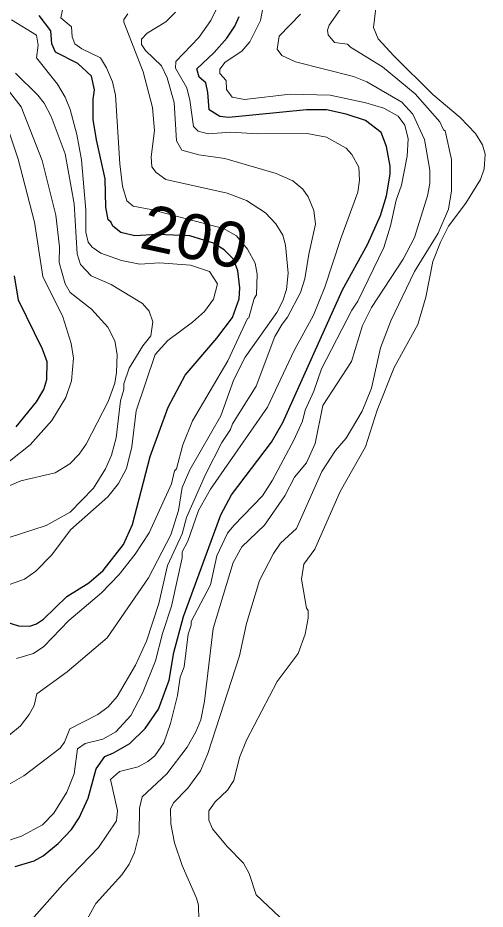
# Model space of a CAD drawing. Extents: x 474.5 to 500, y 7345.7 to 7373.4.
# Drawn here: x 475.444 to 476.272, y 7368.127 to 7369.706 of the extents above; entities that cross this region are included whole.
import ezdxf
from ezdxf.enums import TextEntityAlignment as Align

# ---------------------------------------------------------------- set-up
doc = ezdxf.new("R2010")
doc.units = 0
doc.header["$LTSCALE"] = 0.032
doc.layers.add('1', color=7, linetype='Continuous', lineweight=25)
doc.layers.add('2', color=7, linetype='Continuous', lineweight=13)
doc.layers.add('61', color=7, linetype='Continuous')

msp = doc.modelspace()

# ---------------------------------------------------------------- linework, layer by layer
at = {"layer": '1'}
for points in [[(475.4228, 7368.6359), (475.4455, 7368.6288), (475.4655, 7368.6284), (475.4774, 7368.6321), (475.4899, 7368.6407), (475.5308, 7368.6809), (475.5702, 7368.7052), (475.5951, 7368.7269), (475.6313, 7368.7727), (475.6471, 7368.8086), (475.6788, 7368.9289), (475.7107, 7369.0163), (475.741, 7369.0729), (475.7968, 7369.1383), (475.8249, 7369.1752), (475.8364, 7369.2082), (475.8377, 7369.2276), (475.8338, 7369.2579), (475.8263, 7369.2784), (475.8098, 7369.2953), (475.7912, 7369.3068), (475.7488, 7369.3202), (475.6909, 7369.3222), (475.6514, 7369.32), (475.6265, 7369.3258), (475.6127, 7369.337), (475.6088, 7369.3449), (475.604, 7369.3484), (475.6001, 7369.371), (475.5991, 7369.4212), (475.5835, 7369.4898), (475.5777, 7369.5259), (475.5777, 7369.562), (475.58, 7369.5789), (475.5744, 7369.6029), (475.5505, 7369.6251), (475.5107, 7369.6453), (475.5043, 7369.6604), (475.5027, 7369.6832), (475.4818, 7369.7104)], [(475.7834, 7369.5434), (475.781, 7369.5741), (475.7772, 7369.591), (475.7657, 7369.6009), (475.7613, 7369.6161), (475.7924, 7369.6448), (475.8147, 7369.6701), (475.8285, 7369.6916), (475.8362, 7369.7084)], [(475.4391, 7368.2021), (475.4732, 7368.2121), (475.4889, 7368.221), (475.5156, 7368.2428), (475.5391, 7368.268), (475.5531, 7368.2884), (475.5689, 7368.3235), (475.583, 7368.3752), (475.5984, 7368.3974), (475.6139, 7368.4036), (475.6426, 7368.42), (475.6699, 7368.4467), (475.6932, 7368.481), (475.7125, 7368.5325), (475.7207, 7368.5814), (475.7376, 7368.6452), (475.8041, 7368.8256), (475.8227, 7368.8612), (475.8939, 7368.9544), (475.9137, 7368.9889), (476.0195, 7369.2245), (476.0642, 7369.3045), (476.0867, 7369.3558), (476.0978, 7369.3909), (476.1042, 7369.4293), (476.1041, 7369.4436), (476.0978, 7369.4781), (476.088, 7369.5033), (476.0606, 7369.5241), (476.0263, 7369.5358), (475.9912, 7369.543), (475.9555, 7369.543), (475.8179, 7369.5295), (475.8024, 7369.5312), (475.7834, 7369.5434)], [(475.4412, 7368.9813), (475.4773, 7369.0255), (475.49, 7369.0479), (475.4954, 7369.0651), (475.4962, 7369.0967), (475.4878, 7369.1191), (475.4455, 7369.2058), (475.438, 7369.2489)]]:
    msp.add_lwpolyline(points, dxfattribs=at)
at = {"layer": '2'}
for points in [[(475.9088, 7368.1125), (475.8665, 7368.1519), (475.8542, 7368.1898), (475.8443, 7368.2082), (475.815, 7368.2377), (475.7892, 7368.2688), (475.7827, 7368.2847), (475.7826, 7368.3007), (475.794, 7368.317), (475.8157, 7368.3373), (475.8272, 7368.3549), (475.837, 7368.3953), (475.8494, 7368.4264), (475.9038, 7368.5304), (475.9413, 7368.5799), (475.9536, 7368.6142), (475.9589, 7368.6423), (475.9589, 7368.6557), (475.9558, 7368.6603), (475.9471, 7368.7117), (475.9512, 7368.738), (475.9704, 7368.7649), (476.0154, 7368.8668), (476.0601, 7368.9458), (476.0811, 7369.0112), (476.1112, 7369.0865), (476.153, 7369.163), (476.1671, 7369.2115), (476.18, 7369.2742), (476.1932, 7369.3087), (476.2077, 7369.337), (476.2384, 7369.3781), (476.264, 7369.4198), (476.2709, 7369.4386), (476.2725, 7369.4648), (476.2679, 7369.4812), (476.2554, 7369.5011), (476.2282, 7369.5299), (476.1799, 7369.5701), (476.1105, 7369.6387), (476.083, 7369.669), (476.0746, 7369.6891), (476.0802, 7369.739)], [(475.884, 7369.7526), (475.8744, 7369.7018), (475.8555, 7369.664), (475.8411, 7369.6469), (475.8116, 7369.6274)], [(476.0198, 7369.7272), (475.9962, 7369.6933), (475.9933, 7369.6842), (475.9939, 7369.6763)], [(475.4115, 7368.243), (475.4509, 7368.2558), (475.4881, 7368.276), (475.5082, 7368.297), (475.5312, 7368.3342), (475.5441, 7368.3664), (475.5499, 7368.411), (475.5636, 7368.4205), (475.5945, 7368.4281), (475.6177, 7368.4407), (475.6445, 7368.4698), (475.6653, 7368.5097), (475.688, 7368.5666), (475.7006, 7368.6155), (475.7166, 7368.6637), (475.7356, 7368.7492), (475.7357, 7368.7597), (475.7454, 7368.7787), (475.7643, 7368.8334), (475.7854, 7368.8711), (475.8866, 7369.0163), (475.9337, 7369.1168), (475.9683, 7369.1795), (475.9881, 7369.2289), (476.0168, 7369.315), (476.0467, 7369.3971), (476.0499, 7369.4187), (476.0483, 7369.4417), (476.0363, 7369.464), (476.0262, 7369.475), (475.9911, 7369.4945), (475.9569, 7369.5015), (475.869, 7369.5007), (475.8215, 7369.5039), (475.7813, 7369.5008), (475.764, 7369.5056), (475.7555, 7369.5138), (475.749, 7369.5603), (475.7435, 7369.5821), (475.7237, 7369.6173), (475.724, 7369.6289), (475.7647, 7369.6712), (475.7865, 7369.7015), (475.7954, 7369.7209)], [(475.5235, 7369.7203), (475.5202, 7369.706), (475.539, 7369.6901), (475.5407, 7369.6724), (475.5452, 7369.6602), (475.5577, 7369.6512), (475.5904, 7369.6354), (475.6014, 7369.6175), (475.612, 7369.5931), (475.6175, 7369.5693), (475.6248, 7369.4476), (475.6296, 7369.408), (475.6374, 7369.382), (475.6484, 7369.3724), (475.6797, 7369.3663), (475.8089, 7369.3327), (475.8318, 7369.3202), (475.8514, 7369.2964), (475.8648, 7369.2715), (475.8681, 7369.2517), (475.8672, 7369.2152)], [(475.5609, 7368.0981), (475.5826, 7368.1368), (475.6287, 7368.1876), (475.6413, 7368.2066), (475.6508, 7368.227), (475.659, 7368.2604), (475.6598, 7368.3055), (475.6647, 7368.3256), (475.7081, 7368.3668), (475.7444, 7368.414), (475.7599, 7368.4407), (475.7683, 7368.4621), (475.7747, 7368.4953), (475.7904, 7368.6239), (475.8256, 7368.7412), (475.8411, 7368.7686), (475.8814, 7368.8073), (475.9174, 7368.8591), (475.9347, 7368.8923), (475.956, 7368.9178), (475.971, 7368.9522), (475.9847, 7369.0192), (476.0355, 7369.0971), (476.0549, 7369.1609), (476.0708, 7369.1931), (476.1272, 7369.2787), (476.147, 7369.3167), (476.1704, 7369.3909), (476.1743, 7369.4124), (476.1743, 7369.4364), (476.1649, 7369.4909), (476.1442, 7369.5356), (476.1246, 7369.557), (476.0625, 7369.5926), (476.0393, 7369.6021), (475.936, 7369.6285), (475.9121, 7369.6392), (475.904, 7369.6507), (475.9072, 7369.6738), (475.9454, 7369.7125)], [(475.8267, 7369.0654), (475.8472, 7369.1048), (475.903, 7369.1838), (475.9141, 7369.205), (475.9206, 7369.2247), (475.923, 7369.254), (475.9183, 7369.3032), (475.9139, 7369.3211), (475.9015, 7369.3412), (475.8829, 7369.3605), (475.8497, 7369.3826), (475.8152, 7369.3955), (475.7063, 7369.4198), (475.6891, 7369.4324), (475.6819, 7369.4424), (475.6806, 7369.4598), (475.6861, 7369.5066), (475.6829, 7369.5473), (475.6663, 7369.6106), (475.632, 7369.6986), (475.632, 7369.703), (475.639, 7369.7136)], [(475.7238, 7369.7164), (475.7065, 7369.6991), (475.6732, 7369.6792), (475.6631, 7369.6682), (475.6631, 7369.6588), (475.6703, 7369.6482), (475.6988, 7369.6214), (475.709, 7369.6002), (475.7211, 7369.5561), (475.7252, 7369.4882), (475.7351, 7369.4719), (475.7649, 7369.4634), (475.8109, 7369.4568), (475.9022, 7369.4301), (475.9313, 7369.4172), (475.9494, 7369.4026), (475.9589, 7369.3891), (475.9686, 7369.3649)], [(475.4072, 7368.6943), (475.4562, 7368.7113), (475.4763, 7368.7255), (475.5041, 7368.7546), (475.5374, 7368.7992), (475.6034, 7368.8572), (475.6227, 7368.8812), (475.6367, 7368.9075), (475.6463, 7368.9458), (475.6536, 7369.0099), (475.6876, 7369.1096), (475.7101, 7369.1344), (475.7536, 7369.1668), (475.7747, 7369.1857), (475.7907, 7369.2074), (475.7979, 7369.2349), (475.7841, 7369.2566), (475.7499, 7369.2678), (475.6952, 7369.2718), (475.6604, 7369.2695), (475.6281, 7369.2763), (475.5915, 7369.2892), (475.5758, 7369.3001), (475.5688, 7369.3088), (475.5649, 7369.3265), (475.5649, 7369.3654), (475.5569, 7369.4547), (475.5488, 7369.4997), (475.537, 7369.5436), (475.5283, 7369.5659), (475.5146, 7369.5885), (475.4772, 7369.6351), (475.4802, 7369.6578), (475.477, 7369.6754), (475.4327, 7369.7024)], [(475.9939, 7369.6763), (476.0055, 7369.6627), (476.0282, 7369.6595), (476.034, 7369.654), (476.0906, 7369.6195), (476.1484, 7369.5714), (476.1921, 7369.522), (476.1985, 7369.508), (476.2016, 7369.5058), (476.2126, 7369.455), (476.2126, 7369.3997), (476.2077, 7369.3674), (476.1892, 7369.3245), (476.1474, 7369.2569), (476.1051, 7369.1691), (476.0867, 7369.1213), (476.0709, 7369.0501), (476.0546, 7369.0091), (476.0261, 7368.9615), (476.0072, 7368.9396), (475.9829, 7368.9023), (475.938, 7368.801), (475.9097, 7368.7755), (475.8974, 7368.757), (475.8727, 7368.7091), (475.8496, 7368.6328), (475.8371, 7368.5759), (475.7811, 7368.4027), (475.7678, 7368.3717), (475.7457, 7368.3412), (475.7203, 7368.3151), (475.715, 7368.3038), (475.7152, 7368.2782), (475.7218, 7368.2443), (475.7355, 7368.2041), (475.761, 7368.1464), (475.7643, 7368.1337), (475.7651, 7368.1076)], [(475.8116, 7369.6274), (475.8019, 7369.6153), (475.802, 7369.6075), (475.8135, 7369.5949), (475.8138, 7369.579), (475.824, 7369.5655), (475.8458, 7369.5613), (475.927, 7369.5709), (475.9975, 7369.5693), (476.0609, 7369.5559), (476.093, 7369.5462), (476.1181, 7369.5322), (476.1301, 7369.5159), (476.136, 7369.4916), (476.1345, 7369.4611), (476.1241, 7369.4098), (476.1147, 7369.3829), (476.1048, 7369.3375), (476.0928, 7369.2992), (476.047, 7369.2044), (476.0361, 7369.1883), (475.9821, 7369.0844), (475.9685, 7369.0447), (475.9534, 7369.0107), (475.9485, 7368.9916), (475.9333, 7368.9581), (475.8954, 7368.8869), (475.878, 7368.859), (475.8267, 7368.8069), (475.816, 7368.7929), (475.797, 7368.753), (475.7857, 7368.7012), (475.7516, 7368.6364), (475.7515, 7368.6299), (475.7459, 7368.6142), (475.7388, 7368.5563), (475.7316, 7368.5376), (475.7269, 7368.5056), (475.7148, 7368.456), (475.7028, 7368.4212), (475.6869, 7368.3983), (475.6745, 7368.3881), (475.6572, 7368.3791), (475.6244, 7368.3705), (475.6081, 7368.3567), (475.6207, 7368.3015), (475.6192, 7368.283), (475.5869, 7368.236), (475.5236, 7368.1703), (475.4502, 7368.0873)], [(475.44, 7369.6084), (475.4796, 7369.5693), (475.4907, 7369.555), (475.5031, 7369.5316), (475.5283, 7369.4654), (475.5441, 7369.3769), (475.549, 7369.2883), (475.5551, 7369.2692), (475.5742, 7369.2488), (475.6098, 7369.2334), (475.6652, 7369.2002), (475.6771, 7369.1866), (475.6836, 7369.1676), (475.6796, 7369.1426), (475.6657, 7369.1247), (475.6412, 7369.0854), (475.6321, 7369.0578), (475.6319, 7369.0476), (475.6262, 7369.0275), (475.6184, 7368.9617), (475.61, 7368.9311), (475.5998, 7368.907), (475.5785, 7368.8728), (475.5371, 7368.83), (475.4945, 7368.8066), (475.427, 7368.7849)], [(475.4106, 7368.8692), (475.4495, 7368.8857), (475.5104, 7368.9), (475.5363, 7368.9161), (475.5528, 7368.9333), (475.5655, 7368.9509), (475.6045, 7369.0263), (475.6159, 7369.0588), (475.6193, 7369.0778), (475.62, 7369.1095), (475.616, 7369.134), (475.6038, 7369.158), (475.5749, 7369.19), (475.537, 7369.2193), (475.5281, 7369.2346), (475.5171, 7369.2724), (475.5178, 7369.3003), (475.5115, 7369.3568), (475.4872, 7369.4537), (475.4499, 7369.5488), (475.425, 7369.5807)], [(475.4285, 7369.5037), (475.4445, 7369.4558), (475.4739, 7369.3444), (475.4883, 7369.2481), (475.5239, 7369.1766), (475.5385, 7369.1293), (475.5426, 7369.1031), (475.5394, 7369.063), (475.529, 7369.0333), (475.5044, 7368.9928), (475.4659, 7368.9495), (475.4145, 7368.9088)], [(475.9686, 7369.3649), (475.9718, 7369.3406), (475.9598, 7369.2872), (475.953, 7369.2438), (475.9452, 7369.2194), (475.9224, 7369.1755), (475.9124, 7369.1636), (475.8998, 7369.1415), (475.8663, 7369.0538), (475.8247, 7368.9865), (475.8213, 7368.9768), (475.806, 7368.9538), (475.7769, 7368.8971), (475.7433, 7368.8205), (475.7354, 7368.7918), (475.7096, 7368.7359), (475.6942, 7368.6682), (475.6721, 7368.6018), (475.6525, 7368.5592), (475.6199, 7368.5035), (475.6045, 7368.4851), (475.5857, 7368.4714), (475.536, 7368.446), (475.5269, 7368.4226), (475.5193, 7368.4119), (475.4548, 7368.3631), (475.3588, 7368.3088)], [(475.8672, 7369.2152), (475.8633, 7369.2087), (475.8536, 7369.1747), (475.8511, 7369.1733), (475.8164, 7369.0983), (475.7537, 7368.992), (475.7365, 7368.9498), (475.7252, 7368.9073), (475.7221, 7368.9037), (475.7164, 7368.8802), (475.6772, 7368.7937), (475.6521, 7368.756), (475.6238, 7368.7195), (475.5922, 7368.6872), (475.5347, 7368.6385), (475.4903, 7368.5922), (475.4719, 7368.5796), (475.4417, 7368.5707)], [(475.4067, 7368.4173), (475.4486, 7368.4518), (475.4642, 7368.4714), (475.473, 7368.4874), (475.478, 7368.5082), (475.5314, 7368.5473), (475.6026, 7368.6074), (475.6756, 7368.7139), (475.7154, 7368.7902), (475.7291, 7368.8333), (475.7357, 7368.874), (475.7489, 7368.9051), (475.8041, 7369.0011), (475.8267, 7369.0654)]]:
    msp.add_lwpolyline(points, dxfattribs=at)

# ---------------------------------------------------------------- texts
at = {"layer": '61', "width": 1.05}
msp.add_text('200', height=0.08, rotation=347.812, dxfattribs=at).set_placement((475.7488, 7369.2793), align=Align.CENTER)

doc.saveas('drawing.dxf')
